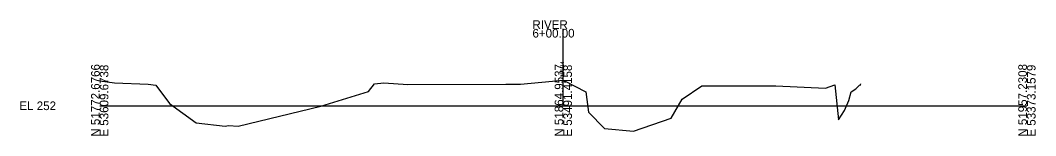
# Model space of a CAD drawing. Extents: x 5628 to 5956, y 92469 to 104012.
# Drawn here: x 5627.6 to 5956.2, y 95468.9 to 95506.3 of the extents above; entities that cross this region are included whole.
import ezdxf

# ---------------------------------------------------------------- set-up
doc = ezdxf.new("R2010")
doc.units = 0
for name, color, linetype in [('Level 10', 7, 'Continuous'), ('Level 60', 7, 'Continuous'), ('Level 63', 7, 'Continuous')]:
    doc.layers.add(name, color=color, linetype=linetype)

msp = doc.modelspace()

# ---------------------------------------------------------------- linework, layer by layer
at = {"layer": 'Level 60'}
for p, q in [((5653.34, 95486.67), (5658.09, 95486)), ((5658.09, 95486), (5669.04, 95485.61)), ((5669.04, 95485.61), (5671.45, 95485.25)), ((5671.45, 95485.25), (5675.95, 95479.32)), ((5740.26, 95483.2), (5742.28, 95485.68)), ((5742.28, 95485.68), (5745.28, 95486)), ((5745.28, 95486), (5753.06, 95485.44)), ((5753.06, 95485.44), (5784.75, 95485.59)), ((5784.75, 95485.59), (5789.49, 95485.56)), ((5789.49, 95485.56), (5803.34, 95486.88)), ((5803.34, 95486.88), (5803.73, 95486.67)), ((5803.73, 95486.67), (5810.64, 95483.07)), ((5888.14, 95484.29), (5891.18, 95485.37)), ((5891.18, 95485.37), (5892.39, 95474.04)), ((5898.66, 95484.71), (5899.23, 95485.38)), ((5899.23, 95485.38), (5899.46, 95485.24)), ((5899.46, 95485.24), (5899.63, 95485.68)), ((5724.87, 95478.47), (5740.26, 95483.2)), ((5810.64, 95483.07), (5811.53, 95476.52)), ((5841.8, 95480.69), (5848.13, 95485.01)), ((5848.13, 95485.01), (5870.86, 95485.05)), ((5870.86, 95485.05), (5872.08, 95485.07)), ((5872.08, 95485.07), (5888.14, 95484.29)), ((5895.69, 95480.34), (5896.42, 95483.1)), ((5896.42, 95483.1), (5898.02, 95484.05)), ((5898.02, 95484.05), (5898.66, 95484.71)), ((5675.95, 95479.32), (5684.52, 95473.07)), ((5838.23, 95474.64), (5841.8, 95480.69)), ((5894.3, 95477.04), (5895.69, 95480.34)), ((5698.18, 95471.97), (5724.87, 95478.47)), ((5811.53, 95476.52), (5816.63, 95471.21)), ((5892.39, 95474.04), (5894.3, 95477.04)), ((5684.52, 95473.07), (5693.97, 95472.01)), ((5693.97, 95472.01), (5694.99, 95472.21)), ((5694.99, 95472.21), (5698.18, 95471.97)), ((5826.01, 95470.34), (5838.23, 95474.64)), ((5816.63, 95471.21), (5826.01, 95470.34))]:
    msp.add_line(p, q, dxfattribs=at)
at = {"layer": 'Level 63'}
for p, q in [((5803.34, 95478.6), (5803.34, 95503.5)), ((5653.34, 95478.6), (5803.34, 95478.6)), ((5803.34, 95478.6), (5953.34, 95478.6))]:
    msp.add_line(p, q, dxfattribs=at)

# ---------------------------------------------------------------- texts
at = {"layer": 'Level 10'}
msp.add_text('256.14', height=1.2, rotation=90, dxfattribs=at).set_placement((5803.54, 95487.88))
at = {"layer": 'Level 63'}
for s, p in [('RIVER', (5793.34, 95503.5)), ('6+00.00', (5793.34, 95500.7)), ('EL 252', (5627.33, 95477.2))]:
    msp.add_text(s, height=2.8, dxfattribs=at).set_placement(p)
for s, p in [('N 51772.6766', (5653.34, 95468.59)), ('E 53609.6738', (5656.14, 95468.6)), ('N 51864.9537', (5803.34, 95468.6)), ('E 53491.4158', (5806.14, 95468.6)), ('N 51957.2308', (5953.34, 95468.6)), ('E 53373.1579', (5956.14, 95468.6))]:
    msp.add_text(s, height=2.8, rotation=90, dxfattribs=at).set_placement(p)

doc.saveas('drawing.dxf')
